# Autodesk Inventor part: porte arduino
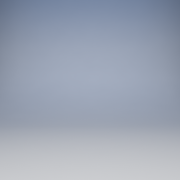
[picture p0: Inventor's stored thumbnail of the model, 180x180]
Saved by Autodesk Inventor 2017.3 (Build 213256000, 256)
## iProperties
Part Number: porte arduino
Material: Générique
Document SubType Name: Modeling
Designer: ficho
Density: 1 g/cm^3
Appearance: Par défaut
Author: ficho
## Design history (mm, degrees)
